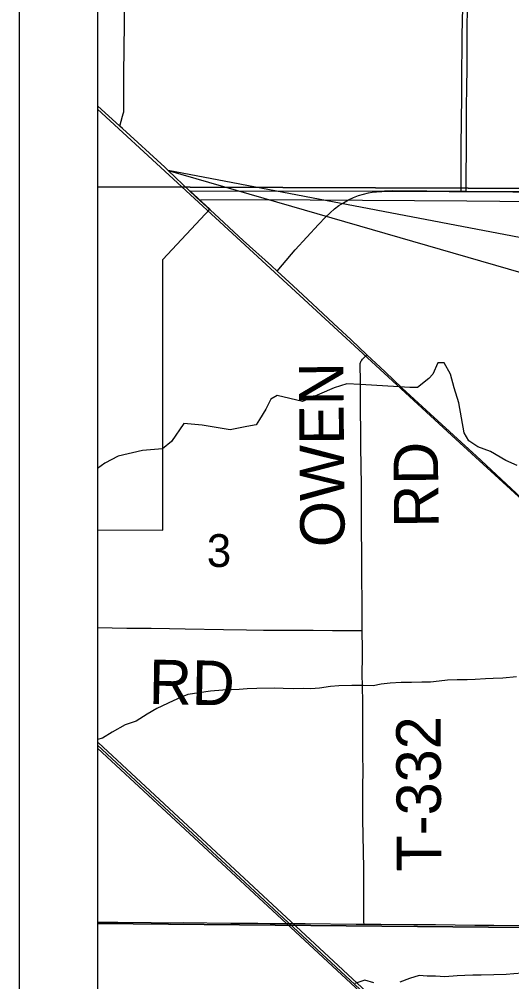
# Model space of a CAD drawing. Extents: x 0 to 34, y 0 to 22.
# Drawn here: x 2 to 2.63, y 19.337 to 20.568 of the extents above; entities that cross this region are included whole.
import ezdxf

# ---------------------------------------------------------------- set-up
doc = ezdxf.new("R2010")
doc.units = 0
for name, color, linetype in [('Default', 7, 'Continuous'), ('GM_X_City_Street', 7, 'Continuous'), ('GM_X_Interstate_Route', 7, 'Continuous'), ('GM_X_Minor_River', 7, 'Continuous'), ('GM_X_Rail_Line', 7, 'Continuous'), ('GM_X_Section_Text', 7, 'Continuous'), ('GM_X_State_Route', 7, 'Continuous'), ('GM_X_Township_Road', 7, 'Continuous'), ('GM_X_Township_Road_Text', 7, 'Continuous'), ('SH_Data', 7, 'Continuous'), ('SH_Text', 7, 'Continuous')]:
    doc.layers.add(name, color=color, linetype=linetype)

msp = doc.modelspace()

# ---------------------------------------------------------------- linework, layer by layer
at = {"layer": 'Default'}
for points in [[(2.6946, 20.9), (2.1, 20.9), (2.1, 20.3537), (2.6925, 20.3513)], [(2.1, 20.3537), (2.1, 19.4117), (2.6907, 19.4065), (2.6925, 20.3513)], [(2.1, 19.4117), (2.1, 18.4052), (2.6966, 18.4009), (2.6907, 19.4065)]]:
    msp.add_lwpolyline(points, close=True, dxfattribs=at)
msp.add_lwpolyline([(2.1, 20.9), (2.1, 19.9153), (2.1835, 19.9146), (2.1838, 20.2606), (2.2438, 20.3249), (2.218, 20.3487), (2.4565, 20.3479), (2.4779, 20.3488), (2.5649, 20.3481), (2.5712, 20.3481), (2.6426, 20.3477)], dxfattribs=at)
at = {"layer": 'GM_X_City_Street'}
for points in [[(2.5651, 20.3475), (2.5651, 20.354), (2.5651, 20.366), (2.5652, 20.3857), (2.5652, 20.4056), (2.5659, 20.4696), (2.5662, 20.4864), (2.5666, 20.5473), (2.5671, 20.5833), (2.5673, 20.5917), (2.5673, 20.5929), (2.5675, 20.5947), (2.5678, 20.5959), (2.5684, 20.597), (2.5691, 20.5979), (2.5703, 20.5988)], [(2.5715, 20.3475), (2.5715, 20.364), (2.5718, 20.4053), (2.5719, 20.4345), (2.572, 20.4532), (2.5723, 20.4831), (2.5726, 20.5023), (2.5726, 20.5316), (2.5729, 20.5553), (2.5731, 20.5832), (2.5732, 20.5922), (2.5732, 20.5942), (2.5728, 20.5959), (2.5723, 20.5971), (2.5716, 20.5978), (2.5703, 20.5988)], [(2.1285, 20.4314), (2.1322, 20.444), (2.1331, 20.447), (2.1336, 20.4495), (2.1338, 20.4524), (2.1338, 20.4596), (2.1337, 20.4778), (2.1337, 20.4865), (2.1337, 20.4983), (2.135, 20.5946)]]:
    msp.add_lwpolyline(points, dxfattribs=at)
at = {"layer": 'GM_X_Interstate_Route'}
msp.add_lwpolyline([(4.7088, 20.9), (2.1, 20.9), (2.1, 14.3639)], dxfattribs=at)
at = {"layer": 'GM_X_Minor_River'}
for points in [[(3.6572, 20.3291), (3.4193, 20.3302), (3.2971, 20.3299), (3.1571, 20.3295), (3.0421, 20.331), (2.8477, 20.333), (2.6994, 20.3342), (2.5723, 20.3352), (2.3722, 20.3365), (2.2322, 20.3372)], [(2.6366, 19.9976), (2.6223, 20.0039), (2.6028, 20.0152), (2.5866, 20.0212), (2.575, 20.0289), (2.5688, 20.0393), (2.5622, 20.0773), (2.556, 20.0968), (2.5514, 20.1143), (2.5433, 20.1285), (2.5354, 20.1286), (2.5287, 20.1143), (2.5237, 20.1087), (2.5095, 20.0972), (2.4997, 20.0969), (2.4366, 20.101), (2.4188, 20.102), (2.4028, 20.0966)], [(2.4028, 20.0966), (2.3624, 20.079), (2.3297, 20.0868), (2.3216, 20.082), (2.3154, 20.0696), (2.3072, 20.0564), (2.303, 20.0493), (2.2912, 20.0472), (2.2699, 20.043), (2.2341, 20.0489)], [(2.2341, 20.0489), (2.2103, 20.0511), (2.1948, 20.0282), (2.1833, 20.0189), (2.1575, 20.0167), (2.1264, 20.0092), (2.1096, 20.0004), (2.1, 19.9934)], [(2.6361, 19.7271), (2.6183, 19.7255), (2.6061, 19.7253), (2.5963, 19.7247), (2.583, 19.7238), (2.5728, 19.7236), (2.56, 19.7234), (2.5478, 19.7228), (2.5372, 19.7215), (2.5259, 19.7205), (2.5149, 19.7203), (2.5016, 19.7198), (2.4884, 19.72), (2.4744, 19.7191), (2.463, 19.7177), (2.4524, 19.7156), (2.4399, 19.7162), (2.4252, 19.7161), (2.4089, 19.7156), (2.3979, 19.715), (2.3839, 19.7129), (2.3729, 19.712), (2.3631, 19.7121), (2.3513, 19.712), (2.3377, 19.7122), (2.3267, 19.7127), (2.304, 19.7123), (2.2915, 19.7118), (2.2813, 19.7112), (2.2715, 19.7106), (2.2605, 19.71), (2.2446, 19.7087), (2.2158, 19.7047), (2.2063, 19.701), (2.1967, 19.6966), (2.1761, 19.6867), (2.1635, 19.6793), (2.1494, 19.6704), (2.1353, 19.6657), (2.1189, 19.6565), (2.1063, 19.6488), (2.1, 19.6469)], [(2.6972, 19.3596), (2.6824, 19.3572), (2.6695, 19.3536), (2.6547, 19.35), (2.6433, 19.3483), (2.6323, 19.3474), (2.6225, 19.3468), (2.6069, 19.3462), (2.5907, 19.3457), (2.5801, 19.3459), (2.5699, 19.3453), (2.56, 19.3451), (2.5441, 19.3438), (2.5324, 19.3444), (2.5218, 19.3446), (2.5116, 19.3455), (2.4991, 19.3415), (2.4865, 19.3368)], [(2.4536, 19.3362), (2.4419, 19.3394), (2.429, 19.3351)]]:
    msp.add_lwpolyline(points, dxfattribs=at)
at = {"layer": 'GM_X_Rail_Line'}
for points in [[(2.1, 20.4531), (2.5585, 20.0312), (3.0884, 19.5461), (3.6994, 18.9771), (4.1763, 18.5403), (4.7059, 18.0556)], [(2.1, 19.6439), (2.1012, 19.6428), (2.4982, 19.2743), (2.9696, 18.8359), (3.3468, 18.4857), (3.702, 18.1547), (3.9505, 17.921), (4.0191, 17.8627), (4.0357, 17.8486), (4.0945, 17.8067), (4.1695, 17.7587), (4.2566, 17.7148), (4.3444, 17.681), (4.4559, 17.6499), (4.5498, 17.6344), (4.6383, 17.6263), (4.7029, 17.6237), (4.7039, 17.6237)], [(2.1, 19.64), (2.4967, 19.2714), (2.9674, 18.8343), (3.3458, 18.483), (3.6997, 18.1544), (3.9489, 17.9193), (4.0176, 17.861), (4.0342, 17.8468), (4.0931, 17.8048), (4.1683, 17.7567), (4.2556, 17.7127), (4.3436, 17.6788), (4.4554, 17.6477), (4.5495, 17.6321), (4.6381, 17.624), (4.7029, 17.6214), (4.7039, 17.6214)], [(2.1, 19.6361), (2.495, 19.2699), (2.9648, 18.8329), (3.3427, 18.4821), (3.6981, 18.1527), (3.7275, 18.125), (3.7678, 18.0902)]]:
    msp.add_lwpolyline(points, dxfattribs=at)
at = {"layer": 'GM_X_State_Route'}
for p, q in [((2.2182, 20.3482), (2.1904, 20.3744)), ((2.1904, 20.3744), (2.2182, 20.3482))]:
    msp.add_line(p, q, dxfattribs=at)
for points in [[(2.1321, 20.4282), (2.1285, 20.4314), (2.1, 20.4572)], [(2.1904, 20.3744), (2.1861, 20.3786), (2.1321, 20.4282)], [(2.244, 20.3243), (2.2421, 20.3261), (2.2335, 20.3339), (2.2327, 20.3346), (2.2182, 20.3482)], [(2.2182, 20.3482), (2.2327, 20.3346), (2.2335, 20.3339), (2.2421, 20.3261), (2.244, 20.3243)], [(2.3297, 20.2458), (2.3367, 20.254), (2.353, 20.2731), (2.3829, 20.3056), (2.3918, 20.315), (2.3975, 20.3205), (2.4031, 20.3253), (2.4089, 20.3297), (2.4145, 20.3333), (2.421, 20.3369), (2.4276, 20.34), (2.4338, 20.3424), (2.4402, 20.3444), (2.4467, 20.3459), (2.4512, 20.3467), (2.4567, 20.3473)], [(2.4567, 20.3473), (2.4638, 20.3478), (2.4725, 20.348), (2.4956, 20.348), (2.522, 20.3479), (2.5497, 20.3476), (2.5651, 20.3475), (2.5715, 20.3475), (2.5774, 20.3476), (2.6027, 20.3476), (2.6314, 20.3472), (2.6663, 20.347), (2.6878, 20.347)], [(2.4243, 20.1579), (2.4017, 20.179), (2.375, 20.2041), (2.3503, 20.2269), (2.3297, 20.2458), (2.3224, 20.2525), (2.2865, 20.2852), (2.2746, 20.2962), (2.2558, 20.3134), (2.244, 20.3243)], [(2.244, 20.3243), (2.2558, 20.3134), (2.2746, 20.2962), (2.2865, 20.2852), (2.3224, 20.2525), (2.3297, 20.2458), (2.3503, 20.2269), (2.375, 20.2041), (2.4017, 20.179), (2.4243, 20.1579)], [(2.4679, 20.117), (2.4446, 20.1388), (2.4243, 20.1579)], [(2.4243, 20.1579), (2.4446, 20.1388), (2.4679, 20.117)], [(2.6489, 19.9496), (2.6034, 19.9919), (2.5847, 20.0093), (2.5553, 20.0361), (2.5205, 20.068), (2.4898, 20.0962), (2.4679, 20.117)], [(2.4679, 20.117), (2.4898, 20.0962), (2.5205, 20.068), (2.5553, 20.0361), (2.5847, 20.0093), (2.6034, 19.9919), (2.6489, 19.9496)]]:
    msp.add_lwpolyline(points, dxfattribs=at)
at = {"layer": 'GM_X_Township_Road'}
for points in [[(2.4385, 19.7865), (2.4385, 19.7947), (2.4384, 19.8209), (2.4381, 19.8558), (2.4381, 19.8589), (2.4381, 19.8657), (2.4382, 19.8738), (2.4381, 19.8867), (2.4379, 19.8953), (2.4378, 19.905), (2.4376, 19.9145), (2.4375, 19.9245), (2.4375, 19.9335), (2.4375, 19.9437), (2.4375, 19.9538), (2.4375, 19.9699), (2.4375, 19.9749), (2.4373, 19.9941), (2.437, 20.0244), (2.4369, 20.0329), (2.4368, 20.0344), (2.4366, 20.074), (2.4366, 20.0793), (2.4364, 20.0911), (2.4362, 20.1061), (2.4359, 20.1253), (2.4361, 20.1279), (2.4364, 20.1291), (2.4368, 20.1301), (2.4373, 20.1311), (2.4379, 20.1322), (2.4388, 20.1332), (2.4399, 20.1343), (2.4446, 20.1388)], [(2.1, 19.7901), (2.1375, 19.7896), (2.1686, 19.7894), (2.1921, 19.7889), (2.212, 19.7886), (2.2611, 19.7879), (2.2908, 19.7873), (2.3124, 19.7869), (2.3292, 19.7869), (2.3529, 19.7867), (2.3758, 19.7867), (2.4008, 19.7866), (2.4201, 19.7866), (2.4354, 19.7865), (2.4385, 19.7865)], [(2.4409, 19.411), (2.4408, 19.4136), (2.4407, 19.4187), (2.4406, 19.43), (2.4406, 19.4441), (2.4405, 19.4678), (2.4405, 19.4847), (2.4401, 19.5013), (2.4401, 19.5074), (2.44, 19.5205), (2.4396, 19.549), (2.4396, 19.554), (2.4396, 19.5577), (2.4396, 19.5633), (2.4396, 19.5701), (2.4396, 19.5745), (2.4395, 19.577), (2.4396, 19.5936), (2.4397, 19.6008), (2.4397, 19.6065), (2.4396, 19.628), (2.4395, 19.6463), (2.4395, 19.6524), (2.4393, 19.6639), (2.4393, 19.6706), (2.4393, 19.6791), (2.4392, 19.6963), (2.4387, 19.732), (2.4389, 19.752), (2.4388, 19.7643), (2.4385, 19.7843), (2.4385, 19.7865)], [(2.1, 19.4136), (2.1262, 19.4134), (2.1685, 19.4133), (2.1933, 19.4129), (2.2095, 19.413), (2.2704, 19.4124), (2.3052, 19.4122), (2.3208, 19.412), (2.3618, 19.4117), (2.3655, 19.4117), (2.4308, 19.411), (2.4409, 19.411)], [(2.4409, 19.411), (2.4623, 19.4109), (2.5046, 19.4105), (2.5325, 19.4105), (2.5828, 19.4098), (2.607, 19.4097), (2.6424, 19.4092), (2.6685, 19.4088), (2.6913, 19.4088)]]:
    msp.add_lwpolyline(points, dxfattribs=at)
at = {"layer": 'SH_Data'}
for p, q in [((2, 21), (2, 14)), ((2.1, 20.9), (2.1, 14.1))]:
    msp.add_line(p, q, dxfattribs=at)
at = {"layer": 'SH_Text'}
msp.add_lwpolyline([(9.2181, 19.0346), (2.1904, 20.3744), (9.2181, 18.3428)], close=True, dxfattribs=at)

# ---------------------------------------------------------------- texts
at = {"layer": 'GM_X_Section_Text'}
msp.add_text('3', height=0.0419, rotation=0, dxfattribs=at).set_placement((2.2399, 19.8677))
at = {"layer": 'GM_X_Township_Road_Text'}
for s, rotation, p in [('OWEN', 90.4592, (2.4163, 19.8932)), ('RD', 90.4959, (2.5363, 19.9181)), ('RD', 359.0237, (2.1654, 19.6925)), ('T-332', 90.278, (2.5397, 19.4785))]:
    msp.add_text(s, height=0.05682, rotation=rotation, dxfattribs=at).set_placement(p)

doc.saveas('drawing.dxf')
